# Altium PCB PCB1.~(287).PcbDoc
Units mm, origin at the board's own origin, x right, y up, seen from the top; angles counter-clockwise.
Board outline 50.8 x 19 mm, 2 copper layers (Top Layer, Bottom Layer); 25 components, 27 nets, 115 pads, 31 vias.
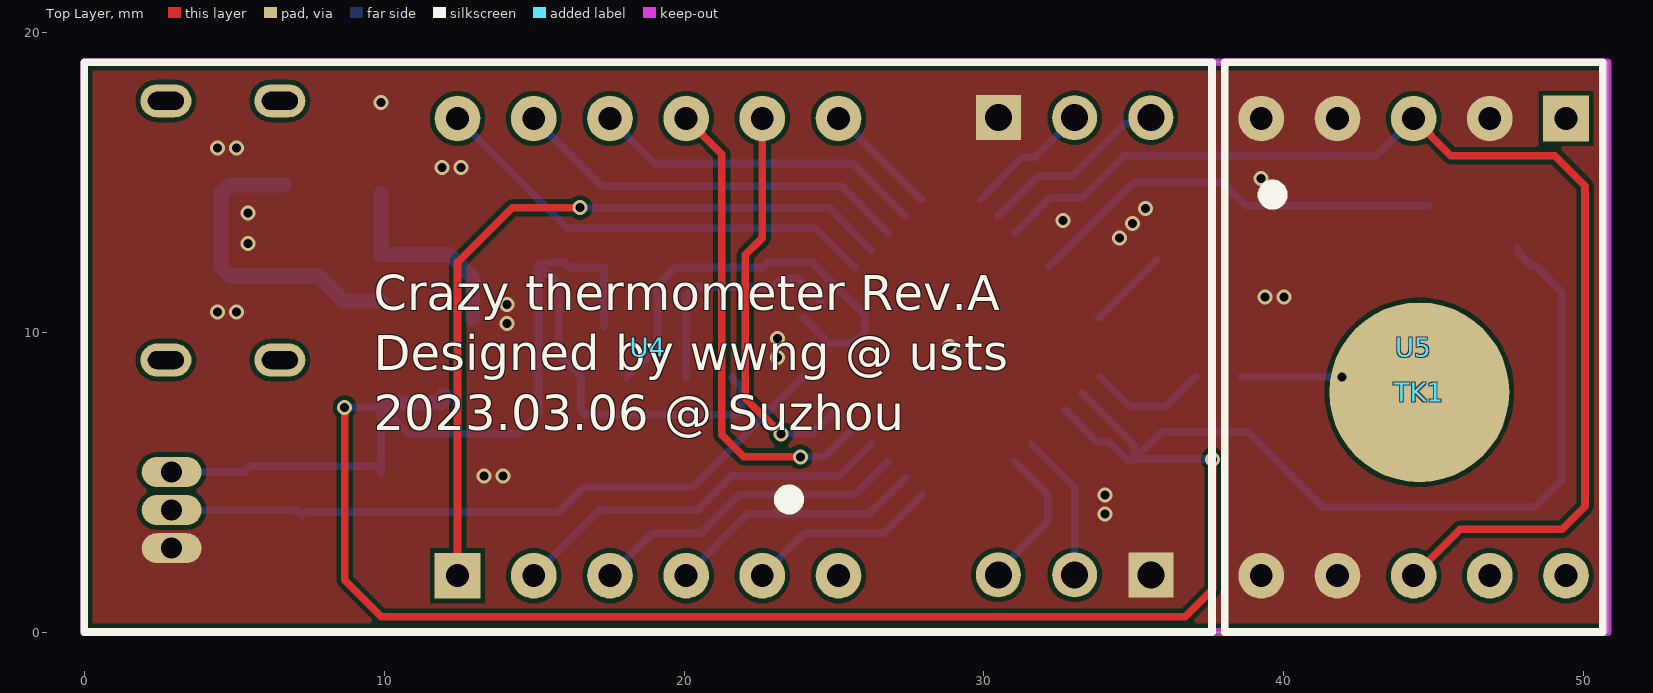
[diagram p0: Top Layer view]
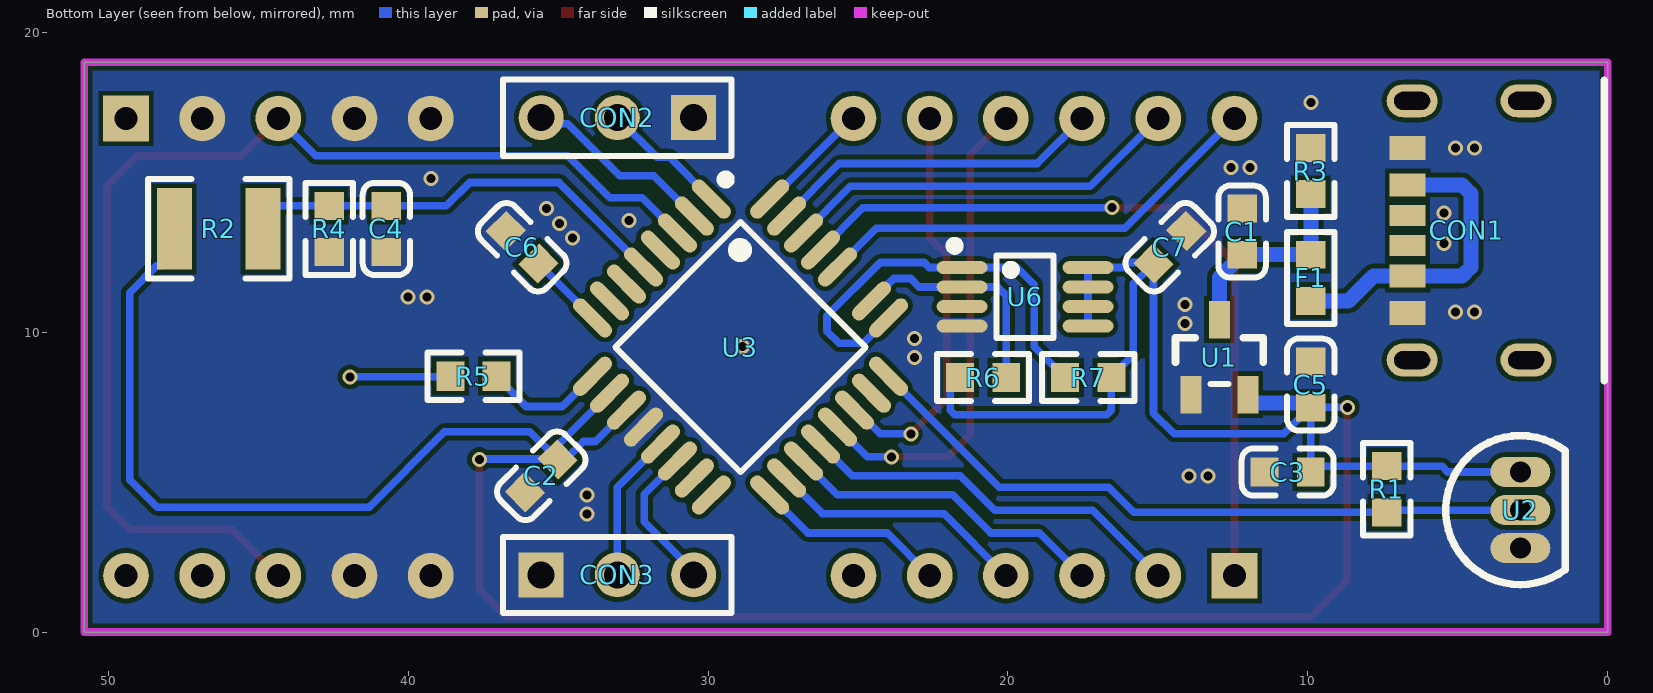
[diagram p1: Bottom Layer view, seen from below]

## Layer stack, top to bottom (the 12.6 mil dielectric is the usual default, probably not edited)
Top Solder: solder mask 0.0102, Solder Resist, Dk 3.5
Top Layer: signal copper 0.0356
Dielectric 1: dielectric 0.32, FR-4, Dk 4.8
Bottom Layer: signal copper 0.0356
Bottom Solder: solder mask 0.0102, Solder Resist, Dk 3.5

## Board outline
0,0 0,19 50.8,19 50.8,0

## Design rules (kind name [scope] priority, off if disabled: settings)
Clearance [All] p1: gap=0.152 ignorepadtopadclearanceinfootprint=FALSE
PolygonConnect [All] p1: connectstyle=Direct reliefconductorwidth=0.254 reliefentries=4 polygonreliefangle="90 Angle" airgapwidth=0.254
RoutingVias [All] p1: holewidth=0.711 width=1.27 viastyle="Through Hole" minholewidth=0.711 minwidth=1.27 maxholewidth=0.711 maxwidth=1.27
SolderMaskExpansion [All] p1: expansion=0.102 istentingtop=FALSE
Width [All] p1: maxlimit=1 minlimit=0.152 preferedwidth=0.254
30 further rules are at their usual default settings.

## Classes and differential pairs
component class Sheet1: C1 C2 C3 C4 C5 C6 C7 CON1 CON2 CON3 F1 R1 R2 R3 R4 R6 R7 U1 U2 U3 U4 U5 U6

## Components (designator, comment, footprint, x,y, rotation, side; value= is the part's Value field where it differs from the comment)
C1 "1uF" 0603_C 12.192,13.348 r270 bottom
C2 "1uF" 0603_C 35.56,5.207 r135 bottom
C3 "0.1uF" 0603_C 10.676,5.334 r180 bottom
C4 "0.1uF" 0603_C 40.725,13.439 r90 bottom
C5 "0.1uF" 0603_C 9.906,8.247 r270 bottom
C6 "0.01uF" 0603_C 36.195,12.827 r225 bottom
C7 "0.1uF" 0603_C 14.605,12.827 r315 bottom
CON1 "USB Type-C" "Type-C 6P" 0.127,13.387 r90 bottom
CON2 "HDR1x3" HDR1x3 30.48,17.145 r0 bottom
CON3 "HDR1x3" HDR1x3 35.56,1.905 r180 bottom
F1 "6V/0.5A" 0603_L 9.906,11.808 r90 bottom
R1 "10K" 0603_R 7.372,4.758 r90 bottom
R2 "GT36516" 1210_R 46.313,13.439 r180 bottom
R3 "10K" 0603_R 9.906,15.367 r90 bottom
R4 "10K" 0603_R 42.631,13.439 r270 bottom
R5 "1K" 0603_R 37.821,8.528 r0 bottom
R6 "10K" 0603_R 20.828,8.484 r180 bottom
R7 "10K" 0603_R 17.323,8.484 r0 bottom
TK1 "Touch Key" TouchKeyD6 44.512,7.993 r0 top
U1 "SC662K-3.3V" SOT-23(SOT-23-3) 12.954,9.164 r270 bottom
U2 "DS18B20" TO-92(TO-92-3) 2.921,4.064 r90 bottom
U3 "STC8H4K64TL-45I-LQFP32" LQFP-32_7x7x08P 28.917,9.5 r315 bottom
U4 "数码管 3P 共阴" "0.56寸 3位" 18.8,9.5 r0 top locked
U5 "数码管 1P 共阳" "0.56寸 1位" 44.323,9.5 r180 top locked
U6 "LM75BDP" MSOP-8 19.431,11.176 r270 bottom

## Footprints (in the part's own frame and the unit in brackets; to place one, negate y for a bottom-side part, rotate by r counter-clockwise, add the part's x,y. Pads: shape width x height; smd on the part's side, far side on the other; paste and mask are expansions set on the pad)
"0.56寸 1位" [mil] "数码管"
  rect 60x60 hole 30: 1(-200,-300)
  round 60 hole 30: 2(-100,-300) 3(0,300) 3(0,-300) 4(100,-300) 5(200,-300) 6(200,300) 7(100,300) 9(-100,300) 10(-200,300)
  silkscreen extent -248,-374 248,374, body extent -248,-374 248,374, height 315
"0.56寸 3位" [mil] "数码管"
  rect 60x60 hole 30: 1(-250,-300)
  round 60 hole 30: 2(-150,-300) 3(-50,-300) 4(50,-300) 5(150,-300) 6(250,-300) 7(250,300) 8(150,300) 9(50,300) 10(-50,300) 11(-150,300) 12(-250,300)
  silkscreen extent -740,-374 740,374, body extent -744,-374 744,374, height 315
0603_C [mm]
  rect 0.93x0.98 smd: 1(-0.77,0) 2(0.77,0)
  silkscreen extent -1.53,-0.79 1.54,0.79, body extent -0.8,-0.4 0.8,0.4, height 0.3
0603_L [mm]
  rect 0.93x0.98 smd: 1(-0.77,0) 2(0.77,0)
  silkscreen extent -1.53,-0.79 1.54,0.79, body extent -0.8,-0.41 0.8,0.41, height 0.46
0603_R [mm]
  rect 0.93x0.98 smd: 1(-0.77,0) 2(0.77,0)
  silkscreen extent -1.53,-0.79 1.54,0.79, body extent -0.85,-0.4 0.85,0.4, height 0.56
1210_R [mm]
  rect 1.16x2.72 smd: 1(-1.475,0) 2(1.475,0)
  silkscreen extent -2.35,-1.66 2.36,1.66, body extent -1.6,-1.25 1.6,1.25, height 0.6
HDR1x3 [mm] "Connector; Header; 3 Position"
  rect 1.5x1.5 hole 0.9: 1(0,0)
  round 1.5 hole 0.9: 2(2.54,0) 3(5.08,0)
  silkscreen extent -1.27,-1.27 6.35,1.27
LQFP-32_7x7x08P [mm]
  oval 0.48x1.65 smd: 1(-2.8,-4.175) 2(-2,-4.175) 3(-1.2,-4.175) 4(-0.4,-4.175) 5(0.4,-4.175) 6(1.2,-4.175) 7(2,-4.175) 8(2.8,-4.175) 17(2.8,4.175) 18(2,4.175) 19(1.2,4.175) 20(0.4,4.175) 21(-0.4,4.175) 22(-1.2,4.175) 23(-2,4.175) 24(-2.8,4.175)
  oval 1.65x0.48 smd: 9(4.175,-2.8) 10(4.175,-2) 11(4.175,-1.2) 12(4.175,-0.4) 13(4.175,0.4) 14(4.175,1.2) 15(4.175,2) 16(4.175,2.8) 25(-4.175,2.8) 26(-4.175,2) 28(-4.175,0.4) 29(-4.175,-0.4) 30(-4.175,-1.2) 31(-4.175,-2) 32(-4.175,-2.8)
  oval 1.65x0.48 on Bottom Overlay: 27(-4.175,1.2)
  silkscreen extent -3.75,-4.45 2.95,2.95
MSOP-8 [mm]
  oval 0.43x1.7 smd mask+0.051: 1(-0.975,-2.1) 2(-0.325,-2.1) 3(0.325,-2.1) 4(0.975,-2.1) 5(0.975,2.1) 6(0.325,2.1) 7(-0.325,2.1) 8(-0.975,2.1)
  silkscreen extent -1.85,-2.5 1.38,0.95
SOT-23(SOT-23-3) [mm]
  rect 1.25x0.7 smd: 1(1.25,-0.95) 2(1.25,0.95) 3(-1.25,0)
  silkscreen extent -0.65,-1.46 0.9,1.46, body extent -1.5,-1.5 1.5,1.5, height 1.3
TO-92(TO-92-3) [mm]
  oval 1x2 hole 0.7 mask+0.051: 1(-1.27,0) 2(0,0) 3(1.27,0)
  silkscreen extent -2.48,-1.5 2.48,2.48, body extent -2.61,-1.6 2.61,2.6, height 8
TouchKeyD6 [mm]
  round 6 smd: 1(0,0)
"Type-C 6P" [mm]
  oval 1.1x1.7 hole 0.6 slot 1.2 at 90 deg: 0(-4.32,6.4) 0(4.32,6.4) 2(-4.32,2.6) 2(4.32,2.6)
  rect 0.7x1.2 smd: A5(-0.5,6.55) B5(0.5,6.55)
  rect 0.76x1.2 smd: A9(1.52,6.55) B9(-1.52,6.55)
  rect 0.8x1.2 smd: A12(2.75,6.55) B12(-2.75,6.55)
  silkscreen extent -5,0 5,0, body extent -4.47,0 4.47,6.8, height 3.2

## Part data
C1 C2 C3 C4 C5 C6 C7: library part "0603 100nF (104) 10% 50V", "贴片电容", Package=0603, SuppliersPartNumber=C14663
F1 R1 R2 R3 R4 R5 R6 R7: library part RES, "Resistor"
U1: library part "AMS1117 3.3V"
U4: library part "数码管 3P"
U5: library part "数码管 1P"

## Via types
v1: diameter 0.5, hole 0.3, Top Layer to Bottom Layer, tented both sides, 31 vias

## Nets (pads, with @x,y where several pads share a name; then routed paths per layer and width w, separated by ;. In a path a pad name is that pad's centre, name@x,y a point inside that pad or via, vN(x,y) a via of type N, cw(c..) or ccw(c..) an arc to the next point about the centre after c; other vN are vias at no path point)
+3.3V: C2.2 C3.2 C5.2 C7.2 R1.2 R2.1 R6.1 R7.1 U1.2 U2.3 U3.10 U3.11 U6.5 U6.6 U6.7 U6.8 | length 113
  Top Layer w0.254: v1(8.687,7.493) 8.687,1.727 9.906,0.508 36.703,0.508 37.622,1.427 v1(37.622,5.751)
  Bottom Layer w0.254: U2.3 5.334,5.334 5.528,5.528 R1.2 9.712,5.528 C3.2 C5.2 ; v1(8.687,7.493) 9.89,7.493 C5.2 ; U6.5 U6.6 U6.7 U6.8 16.17,12.151 16.002,12.319 15.664,12.319 15.645,12.3 15.43,12.3 C7.2@15.281,12.151 ; R6.1 21.92,8.161 21.92,7.388 21.771,7.239 16.702,7.239 16.553,7.388 16.553,8.509 15.824,9.237 15.824,11.608 C7.2@15.281,12.151 ; U3.11 33.764,6.35 34.163,6.35 34.762,5.751 C2.2 ; U3.10 35.016,6.23 C2.2 C2.2@35.033,5.769 ; v1(37.622,5.751) 37.604,5.769 C2.2@35.033,5.769 ; R2.1@47.788,12.804 47.788,12.659 48.241,12.206 48.386,12.206 49.276,11.316 49.276,5.08 48.362,4.166 41.3,4.166 38.786,6.68 35.944,6.68 C2.2@35.033,5.769 ; C5.2 9.931,7.477 10.804,6.604 14.453,6.604 15.149,7.301 C7.2 C7.2@15.281,12.151
  Bottom Layer w0.5: C5.2 10.068,7.639 11.904,7.639 12.004,7.739 U1.2
+5V: C1.2 F1.2 R3.1 U1.3 | length 6.8
  Bottom Layer w0.254: C1.2 C1.2@12.217,12.578
  Bottom Layer w0.5: R3.1 F1.2 C1.2 12.954,11.816 U1.3
COM0: U3.21 U4.9 | length 16.2
  Top Layer w0.254: U4.9 21.26,15.93 21.26,6.579 21.996,5.842 v1(23.876,5.842)
  Bottom Layer w0.254: v1(23.876,5.842) 24.693,5.842 U3.21
COM1: U3.22 U4.8 | length 13.4
  Top Layer w0.254: U4.8@22.61,17.099 22.61,13.136 22.047,12.573 22.047,7.798 v1(23.241,6.604)
  Bottom Layer w0.254: v1(23.241,6.604) 24.263,6.604 25.055,7.396 U3.22
COM7: U3.28 U4.12 | length 15.3
  Bottom Layer w0.254: U4.12 16.108,13.462 24.389,13.462 U3.28
CPMW: U3.3 U5.3 | length 38.9
  Top Layer w0.254: U5.3@44.323,1.88 45.872,3.429 49.276,3.429 50.038,4.191 50.038,14.859 49.022,15.875 45.568,15.875 U5.3@44.323,17.12
  Bottom Layer w0.254: U3.3 32.198,14.478 33.274,14.478 34.671,15.875 43.078,15.875 U5.3@44.323,17.12
DQ: R1.1 U2.2 U3.24 | length 22.9
  Bottom Layer w0.254: U2.2 7.096,4.064 R1.1@7.272,3.888 ; R1.1 15.799,3.988 16.637,4.826 20.283,4.826 U3.24
GND: C1.1 C2.1 C3.1 C4.1 C5.1 C6.1 C7.1 CON1.A12 CON1.B12 CON2.1 CON3.1 R3.2 R4.2 U1.1 U2.1 U3.12 U5.2 U5.4 U5.5 U5.6 U5.7 U6.4
  other v1: 34.036,3.937 34.036,4.572 13.335,5.207 13.97,5.207 23.114,9.144 28.854,9.525 23.114,9.779 14.097,10.287 4.445,10.668 5.08,10.668 14.097,10.922 39.37,11.176 40.005,11.176 5.461,12.954 34.519,13.132 34.95,13.614 32.639,13.716 5.461,13.97 35.382,14.122 39.243,15.113 11.938,15.494 12.573,15.494 4.445,16.129 5.08,16.129 9.906,17.653
GT_ADC: C4.2 R2.2 R4.1 U3.5 | length 14.1
  Bottom Layer w0.254: U3.5 34.969,14.986 37.948,14.986 38.725,14.209 C4.2 R4.1 R2.2@44.806,14.209
NetCON1_A9: CON1.A9 CON1.B9 F1.1 | length 10.5
  Bottom Layer w0.5: CON1.A9 4.865,14.907 4.572,14.614 4.572,12.16 4.865,11.867 CON1.B9 7.818,11.867 8.647,11.038 F1.1
NetR5_2: R5.2 TK1.1 | length 3.4
  Bottom Layer w0.254: R5.2 38.609,8.509 v1(41.935,8.509)
SCL: R6.2 U3.26 U6.2 | length 7.8
  Bottom Layer w0.254: R6.2 20.058,11.219 20.34,11.501 22.956,11.501 23.241,11.786 23.803,11.786 U3.26
SDA: R7.2 U3.25 U6.1 | length 14.6
  Bottom Layer w0.254: R7.2 18.093,8.509 18.431,8.847 18.456,8.847 19.126,9.517 19.126,11.582 19.695,12.151 22.629,12.151 22.797,12.319 24.257,12.319 26.035,10.541 26.035,10.033 25.629,9.627 24.831,9.627 U3.25
SEG8: U3.29 U4.1 | length 25.6
  Top Layer w0.254: U4.1 12.45,12.323 14.275,14.148 v1(16.535,14.148)
  Bottom Layer w0.254: v1(16.535,14.148) 24.835,14.148 U3.29
SEG9: U3.30 U4.11 | length 13.4
  Bottom Layer w0.254: U4.11 17.251,14.859 25.255,14.859 U3.30
SEG10: U3.31 U4.10 | length 11.2
  Bottom Layer w0.254: U4.10 19.029,15.621 25.625,15.621 U3.31
SEG11: U3.32 U4.7 | length 4.1
  Bottom Layer w0.254: U4.7@25.269,17.001 U4.7 25.203,17.12 27.891,14.432 U3.32
SEG12: U3.17 U4.5 | length 6.4
  Bottom Layer w0.254: U4.5 24.032,3.302 26.679,3.302 U3.17
SEG13: U3.18 U4.4 | length 8.7
  Bottom Layer w0.254: U4.4 22.127,3.937 26.183,3.937 U3.18
SEG14: U3.19 U4.3 | length 10.9
  Bottom Layer w0.254: U4.3 18.952,3.302 20.574,3.302 21.844,4.572 25.686,4.572 U3.19
SEG15: U3.20 U4.2 | length 13.1
  Bottom Layer w0.254: U4.2 17.174,4.064 20.447,4.064 21.59,5.207 25.19,5.207 U3.20
STC_RXD: CON3.2 U3.13 | length 5
  Bottom Layer w0.254: U3.13 33.02,4.831 CON3.2
STC_RXD2: CON2.2 U3.1 | length 4.3
  Bottom Layer w0.254: U3.1 31.282,15.824 31.699,15.824 CON2.2
STC_TXD: CON3.3 U3.14 | length 4.9
  Bottom Layer w0.254: CON3.3 30.48,2.032 32.131,3.683 32.131,4.589 U3.14
STC_TXD2: CON2.3 U3.2 | length 6.5
  Bottom Layer w0.254: U3.2 31.803,15.215 32.944,15.215 34.671,16.942 35.357,16.942 CON2.3
TCap: C6.2 U3.8 | length 2.7
  Bottom Layer w0.254: U3.8 35.651,12.274 C6.2 C6.2@35.778,12.41
TK: R5.1 U3.9 | length 4.1
  Bottom Layer w0.254: U3.9 34.859,7.518 36.066,7.518 37.051,8.503 R5.1
pads on no net: CON1.0 CON1.2 CON1.A5 CON1.B5 U3.4 U3.6 U3.7 U3.15 U3.16 U3.23 U3.27 U4.6 U5.1 U5.9 U5.10 U6.3

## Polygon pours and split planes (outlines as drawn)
GND on Top Layer "GND_L01_P000" (solid, pour order 0): 0,19.101 0.127,18.974 50.749,18.974 50.749,0.229 50.521,0 0,0
GND on Bottom Layer "GND_L02_P001" (solid, pour order 1): 0,19.05 50.698,19.05 50.749,18.999 50.724,18.974 50.724,0 0.025,0

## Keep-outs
Keep-Out Layer:
  the board outline again, w0.254

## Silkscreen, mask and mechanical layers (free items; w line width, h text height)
Top Overlay:
  text "Crazy thermometer Rev.A / Designed by wwng @ usts / 2023.03.06 @ Suzhou" at 9.652,6.35 h2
